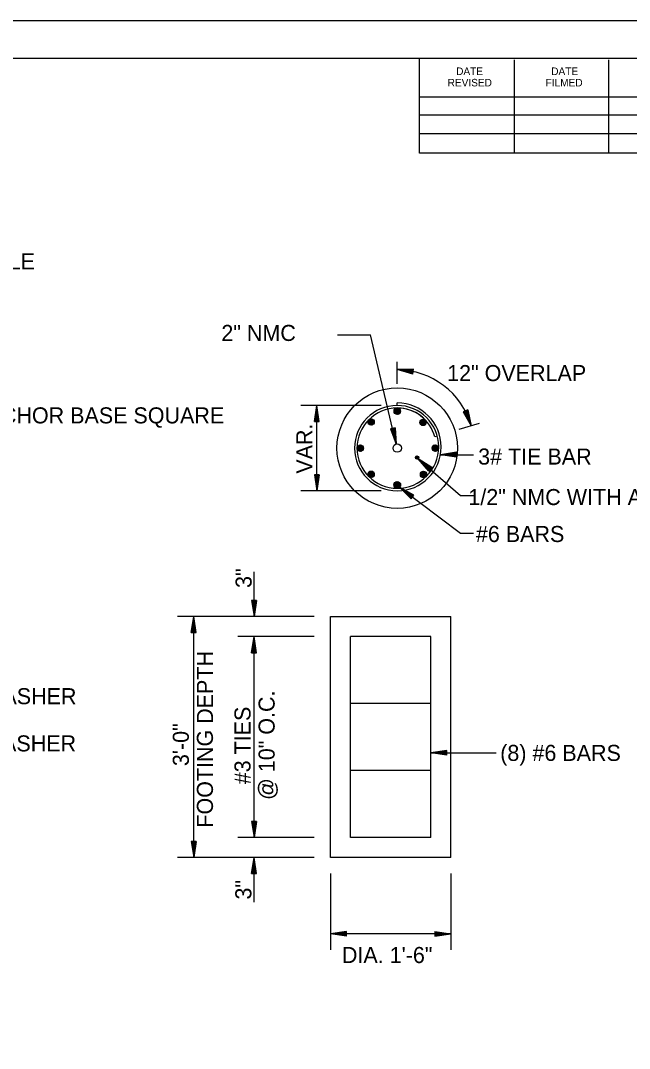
# Model space of a CAD drawing. Extents: x 1370140 to 1371141, y 380020 to 380660.
# Drawn here: x 1370755.4 to 1370944.8, y 380340 to 380660 of the extents above; entities that cross this region are included whole.
import ezdxf

# ---------------------------------------------------------------- set-up
doc = ezdxf.new("R2010")
doc.units = 0
for name, color, linetype in [('R_Border', 7, 'Continuous'), ('R_Draft', 7, 'Continuous'), ('R_No Plot', 7, 'Continuous')]:
    doc.layers.add(name, color=color, linetype=linetype)

msp = doc.modelspace()

# ---------------------------------------------------------------- linework, layer by layer
at = {"layer": 'R_Border'}
for p, q in [((1370177.71, 380648.36), (1371126.25, 380648.36)), ((1370879.47, 380618.72), (1370879.47, 380648.36)), ((1370909.05, 380618.72), (1370909.05, 380647.76)), ((1370938.33, 380618.72), (1370938.33, 380647.76)), ((1370879.47, 380636.3), (1370996.95, 380636.3)), ((1370879.47, 380630.72), (1370996.95, 380630.72)), ((1370879.47, 380618.72), (1370879.47, 380624.9)), ((1370879.47, 380624.9), (1370996.95, 380624.9)), ((1371126.25, 380618.72), (1370879.47, 380618.72))]:
    msp.add_line(p, q, dxfattribs=at)
at = {"layer": 'R_Draft'}
for p, q in [((1370853.99, 380562.21), (1370864.22, 380562.21)), ((1370872.25, 380528.19), (1370864.22, 380562.21)), ((1370872.55, 380546.92), (1370872.55, 380553.77)), ((1370877.61, 380551.48), (1370872.55, 380551.37)), ((1370877.42, 380549.99), (1370872.55, 380551.37)), ((1370877.59, 380551.36), (1370873.38, 380551.27)), ((1370877.43, 380550.12), (1370873.38, 380551.27)), ((1370877.58, 380551.23), (1370874.23, 380551.16)), ((1370877.45, 380550.24), (1370874.23, 380551.16)), ((1370877.56, 380551.11), (1370875.06, 380551.05)), ((1370877.47, 380550.37), (1370875.06, 380551.05)), ((1370877.54, 380550.98), (1370875.9, 380550.94)), ((1370877.48, 380550.5), (1370875.9, 380550.94)), ((1370877.53, 380550.85), (1370876.73, 380550.84)), ((1370877.5, 380550.62), (1370876.73, 380550.84)), ((1370877.42, 380549.99), (1370877.61, 380551.48)), ((1370867.55, 380540.2), (1370842.55, 380540.2)), ((1370846.8, 380535.2), (1370847.55, 380540.2)), ((1370846.92, 380535.2), (1370847.55, 380539.37)), ((1370847.55, 380513.64), (1370847.55, 380540.2)), ((1370848.3, 380535.2), (1370847.55, 380540.2)), ((1370848.17, 380535.2), (1370847.55, 380539.37)), ((1370871.55, 380538.38), (1370872.59, 380539.42)), ((1370871.56, 380538.56), (1370872.41, 380539.41)), ((1370871.57, 380538.22), (1370872.75, 380539.4)), ((1370871.61, 380538.08), (1370872.89, 380539.36)), ((1370871.62, 380538.81), (1370872.16, 380539.34)), ((1370871.66, 380537.96), (1370873.01, 380539.31)), ((1370871.73, 380537.85), (1370873.12, 380539.24)), ((1370871.81, 380537.75), (1370873.22, 380539.16)), ((1370871.89, 380537.66), (1370873.31, 380539.07)), ((1370872, 380537.59), (1370873.38, 380538.97)), ((1370872.11, 380537.52), (1370873.45, 380538.86)), ((1370872.55, 380540.2), (1370872.55, 380540.99)), ((1370847.05, 380535.2), (1370847.55, 380538.51)), ((1370847.17, 380535.2), (1370847.55, 380537.68)), ((1370847.3, 380535.2), (1370847.55, 380536.83)), ((1370847.43, 380535.2), (1370847.55, 380535.99)), ((1370848.04, 380535.2), (1370847.55, 380538.51)), ((1370847.92, 380535.2), (1370847.55, 380537.68)), ((1370847.79, 380535.2), (1370847.55, 380536.83)), ((1370847.66, 380535.2), (1370847.55, 380535.99)), ((1370863.42, 380534.93), (1370864.54, 380536.05)), ((1370863.42, 380535.1), (1370864.37, 380536.05)), ((1370863.45, 380534.78), (1370864.69, 380536.02)), ((1370863.45, 380535.3), (1370864.16, 380536.02)), ((1370863.5, 380534.65), (1370864.82, 380535.97)), ((1370863.56, 380534.53), (1370864.93, 380535.91)), ((1370863.6, 380535.64), (1370863.83, 380535.86)), ((1370863.63, 380534.43), (1370865.04, 380535.84)), ((1370863.72, 380534.34), (1370865.13, 380535.75)), ((1370863.81, 380534.26), (1370865.21, 380535.66)), ((1370872.23, 380537.47), (1370873.5, 380538.73)), ((1370872.38, 380537.44), (1370873.53, 380538.59)), ((1370872.54, 380537.42), (1370873.55, 380538.43)), ((1370872.73, 380537.44), (1370873.53, 380538.24)), ((1370873, 380537.53), (1370873.44, 380537.97)), ((1370879.57, 380534.85), (1370880.66, 380535.94)), ((1370879.57, 380535.03), (1370880.48, 380535.94)), ((1370879.6, 380534.7), (1370880.81, 380535.91)), ((1370879.61, 380535.25), (1370880.26, 380535.89)), ((1370879.64, 380534.56), (1370880.94, 380535.87)), ((1370879.7, 380534.45), (1370881.06, 380535.81)), ((1370879.77, 380534.34), (1370881.17, 380535.74)), ((1370879.85, 380534.24), (1370881.26, 380535.66)), ((1370894.5, 380538.81), (1370893.09, 380538.27)), ((1370893.09, 380538.27), (1370895.58, 380533.87)), ((1370893.21, 380538.32), (1370895.28, 380534.65)), ((1370893.33, 380538.36), (1370894.98, 380535.46)), ((1370893.45, 380538.41), (1370894.68, 380536.23)), ((1370893.57, 380538.45), (1370894.38, 380537.02)), ((1370893.69, 380538.5), (1370894.08, 380537.8)), ((1370893.9, 380538.58), (1370894.08, 380537.8)), ((1370894.02, 380538.63), (1370894.38, 380537.02)), ((1370894.14, 380538.68), (1370894.68, 380536.23)), ((1370894.26, 380538.72), (1370894.98, 380535.46)), ((1370894.38, 380538.77), (1370895.28, 380534.65)), ((1370894.5, 380538.81), (1370895.58, 380533.87)), ((1370846.8, 380535.2), (1370848.3, 380535.2)), ((1370863.92, 380534.19), (1370865.28, 380535.55)), ((1370864.04, 380534.13), (1370865.34, 380535.43)), ((1370864.17, 380534.08), (1370865.38, 380535.3)), ((1370864.32, 380534.06), (1370865.41, 380535.15)), ((1370864.5, 380534.06), (1370865.41, 380534.97)), ((1370864.72, 380534.1), (1370865.37, 380534.75)), ((1370871.86, 380533.23), (1370870.4, 380532.9)), ((1370870.4, 380532.9), (1370872.25, 380528.19)), ((1370870.52, 380532.92), (1370872.06, 380529)), ((1370870.65, 380532.95), (1370871.87, 380529.84)), ((1370870.77, 380532.98), (1370871.68, 380530.65)), ((1370870.89, 380533.01), (1370871.49, 380531.48)), ((1370871.02, 380533.04), (1370871.31, 380532.29)), ((1370871.25, 380533.09), (1370871.31, 380532.29)), ((1370871.37, 380533.12), (1370871.49, 380531.48)), ((1370871.49, 380533.15), (1370871.68, 380530.65)), ((1370871.62, 380533.17), (1370871.87, 380529.84)), ((1370871.74, 380533.2), (1370872.06, 380529)), ((1370871.86, 380533.23), (1370872.25, 380528.19)), ((1370879.94, 380534.16), (1370881.35, 380535.57)), ((1370880.04, 380534.09), (1370881.42, 380535.46)), ((1370880.16, 380534.03), (1370881.48, 380535.35)), ((1370880.29, 380533.98), (1370881.53, 380535.22)), ((1370880.44, 380533.95), (1370881.56, 380535.07)), ((1370880.61, 380533.94), (1370881.56, 380534.9)), ((1370880.81, 380533.97), (1370881.53, 380534.69)), ((1370881.14, 380534.12), (1370881.38, 380534.36)), ((1370897.98, 380534.59), (1370891.69, 380532.7)), ((1370884.99, 380530.68), (1370884.24, 380530.45)), ((1370860.05, 380526.97), (1370861, 380527.92)), ((1370860.05, 380526.8), (1370861.17, 380527.91)), ((1370860.08, 380527.18), (1370860.79, 380527.89)), ((1370860.08, 380526.65), (1370861.32, 380527.88)), ((1370860.13, 380526.52), (1370861.45, 380527.84)), ((1370860.19, 380526.41), (1370861.56, 380527.78)), ((1370860.25, 380527.53), (1370860.44, 380527.72)), ((1370860.26, 380526.3), (1370861.67, 380527.71)), ((1370860.35, 380526.21), (1370861.76, 380527.62)), ((1370860.44, 380526.13), (1370861.84, 380527.53)), ((1370860.55, 380526.06), (1370861.91, 380527.42)), ((1370860.67, 380526), (1370861.97, 380527.3)), ((1370860.8, 380525.95), (1370862.02, 380527.17)), ((1370860.95, 380525.93), (1370862.04, 380527.02)), ((1370861.12, 380525.92), (1370862.04, 380526.85)), ((1370861.34, 380525.97), (1370862, 380526.63)), ((1370883.39, 380526.93), (1370884.38, 380527.92)), ((1370883.4, 380526.77), (1370884.54, 380527.91)), ((1370883.41, 380527.13), (1370884.18, 380527.9)), ((1370883.44, 380526.63), (1370884.69, 380527.88)), ((1370883.48, 380526.5), (1370884.81, 380527.83)), ((1370883.53, 380527.42), (1370883.89, 380527.79)), ((1370883.55, 380526.38), (1370884.93, 380527.76)), ((1370883.62, 380526.28), (1370885.03, 380527.69)), ((1370883.71, 380526.19), (1370885.12, 380527.6)), ((1370883.8, 380526.11), (1370885.2, 380527.51)), ((1370883.91, 380526.04), (1370885.27, 380527.4)), ((1370884.03, 380525.99), (1370885.33, 380527.28)), ((1370884.17, 380525.95), (1370885.37, 380527.14)), ((1370884.32, 380525.92), (1370885.39, 380526.99)), ((1370884.51, 380525.93), (1370885.38, 380526.81)), ((1370884.74, 380525.98), (1370885.33, 380526.57)), ((1370878.19, 380524.01), (1370878.7, 380524.53)), ((1370878.21, 380523.85), (1370878.86, 380524.5)), ((1370878.25, 380524.24), (1370878.47, 380524.47)), ((1370878.26, 380523.73), (1370878.98, 380524.45)), ((1370878.34, 380523.63), (1370879.08, 380524.37)), ((1370878.44, 380523.56), (1370879.16, 380524.27)), ((1370878.57, 380523.5), (1370879.21, 380524.15)), ((1370878.72, 380523.48), (1370879.23, 380523.99)), ((1370878.97, 380523.55), (1370879.16, 380523.74)), ((1370879.08, 380523.63), (1370892.22, 380512.15)), ((1370882.37, 380519.79), (1370879.08, 380523.63)), ((1370883.35, 380520.93), (1370879.08, 380523.63)), ((1370882.45, 380519.89), (1370879.71, 380523.08)), ((1370883.27, 380520.83), (1370879.71, 380523.08)), ((1370891, 380525.62), (1370886, 380524.87)), ((1370886, 380524.87), (1370896.23, 380524.87)), ((1370891, 380524.12), (1370886, 380524.87)), ((1370891, 380525.49), (1370886.84, 380524.87)), ((1370891, 380524.24), (1370886.84, 380524.87)), ((1370891, 380525.36), (1370887.7, 380524.87)), ((1370891, 380524.37), (1370887.7, 380524.87)), ((1370891, 380525.24), (1370888.53, 380524.87)), ((1370891, 380524.49), (1370888.53, 380524.87)), ((1370891, 380525.11), (1370889.38, 380524.87)), ((1370891, 380524.62), (1370889.38, 380524.87)), ((1370891, 380524.98), (1370890.21, 380524.87)), ((1370891, 380524.75), (1370890.21, 380524.87)), ((1370891, 380524.12), (1370891, 380525.62)), ((1370863.42, 380518.7), (1370864.51, 380519.79)), ((1370863.42, 380518.87), (1370864.33, 380519.79)), ((1370863.45, 380518.55), (1370864.66, 380519.76)), ((1370863.46, 380519.09), (1370864.11, 380519.74)), ((1370863.49, 380518.41), (1370864.79, 380519.72)), ((1370863.55, 380518.29), (1370864.91, 380519.66)), ((1370879.73, 380518.79), (1370880.68, 380519.74)), ((1370879.74, 380518.62), (1370880.85, 380519.73)), ((1370879.76, 380519), (1370880.47, 380519.71)), ((1370879.76, 380518.47), (1370881, 380519.7)), ((1370879.81, 380518.34), (1370881.13, 380519.66)), ((1370883.19, 380520.73), (1370880.36, 380522.52)), ((1370882.54, 380519.98), (1370880.36, 380522.52)), ((1370882.62, 380520.08), (1370880.99, 380521.97)), ((1370883.1, 380520.64), (1370880.99, 380521.97)), ((1370883.02, 380520.54), (1370881.63, 380521.42)), ((1370882.7, 380520.17), (1370881.63, 380521.42)), ((1370882.94, 380520.45), (1370882.26, 380520.87)), ((1370882.78, 380520.27), (1370882.26, 380520.87)), ((1370882.37, 380519.79), (1370883.35, 380520.93)), ((1370846.8, 380518.64), (1370847.55, 380513.64)), ((1370848.3, 380518.64), (1370846.8, 380518.64)), ((1370846.92, 380518.64), (1370847.55, 380514.47)), ((1370847.05, 380518.64), (1370847.55, 380515.33)), ((1370847.17, 380518.64), (1370847.55, 380516.17)), ((1370847.3, 380518.64), (1370847.55, 380517.01)), ((1370847.43, 380518.64), (1370847.55, 380517.85)), ((1370848.3, 380518.64), (1370847.55, 380513.64)), ((1370847.79, 380518.64), (1370847.55, 380517.01)), ((1370848.04, 380518.64), (1370847.55, 380515.33)), ((1370848.17, 380518.64), (1370847.55, 380514.47)), ((1370847.92, 380518.64), (1370847.55, 380516.17)), ((1370847.66, 380518.64), (1370847.55, 380517.85)), ((1370863.62, 380518.19), (1370865.02, 380519.59)), ((1370863.7, 380518.09), (1370865.11, 380519.51)), ((1370863.79, 380518.01), (1370865.2, 380519.41)), ((1370863.9, 380517.94), (1370865.27, 380519.31)), ((1370864.01, 380517.87), (1370865.33, 380519.19)), ((1370864.14, 380517.83), (1370865.38, 380519.06)), ((1370864.29, 380517.8), (1370865.41, 380518.92)), ((1370864.46, 380517.79), (1370865.41, 380518.75)), ((1370864.66, 380517.82), (1370865.38, 380518.54)), ((1370865, 380517.98), (1370865.23, 380518.21)), ((1370871.51, 380515.37), (1370872.64, 380516.5)), ((1370871.51, 380515.54), (1370872.47, 380516.5)), ((1370871.53, 380515.22), (1370872.79, 380516.48)), ((1370871.55, 380515.76), (1370872.25, 380516.46)), ((1370871.58, 380515.08), (1370872.93, 380516.43)), ((1370879.87, 380518.22), (1370881.24, 380519.6)), ((1370879.93, 380519.34), (1370880.13, 380519.54)), ((1370879.94, 380518.12), (1370881.35, 380519.52)), ((1370880.03, 380518.03), (1370881.44, 380519.44)), ((1370880.12, 380517.94), (1370881.52, 380519.35)), ((1370880.23, 380517.87), (1370881.59, 380519.24)), ((1370880.35, 380517.82), (1370881.65, 380519.12)), ((1370880.48, 380517.77), (1370881.7, 380518.99)), ((1370880.63, 380517.75), (1370881.72, 380518.84)), ((1370880.81, 380517.74), (1370881.72, 380518.66)), ((1370881.02, 380517.79), (1370881.68, 380518.44)), ((1370867.55, 380513.64), (1370842.55, 380513.64)), ((1370871.63, 380514.96), (1370873.05, 380516.38)), ((1370871.7, 380514.85), (1370873.16, 380516.31)), ((1370871.78, 380514.76), (1370873.25, 380516.23)), ((1370871.78, 380516.17), (1370871.84, 380516.23)), ((1370871.87, 380514.67), (1370873.34, 380516.14)), ((1370871.97, 380514.59), (1370873.42, 380516.04)), ((1370872.09, 380514.53), (1370873.48, 380515.92)), ((1370872.21, 380514.48), (1370873.53, 380515.8)), ((1370872.35, 380514.44), (1370873.57, 380515.66)), ((1370872.51, 380514.42), (1370873.59, 380515.5)), ((1370872.7, 380514.43), (1370873.58, 380515.31)), ((1370872.94, 380514.5), (1370873.51, 380515.07)), ((1370873.29, 380514.73), (1370892.22, 380500.42)), ((1370876.84, 380511.13), (1370873.29, 380514.73)), ((1370877.74, 380512.32), (1370873.29, 380514.73)), ((1370876.91, 380511.23), (1370873.96, 380514.23)), ((1370877.66, 380512.23), (1370873.96, 380514.23)), ((1370877.59, 380512.12), (1370874.65, 380513.71)), ((1370876.99, 380511.33), (1370874.65, 380513.71)), ((1370877.06, 380511.43), (1370875.31, 380513.21)), ((1370877.51, 380512.02), (1370875.31, 380513.21)), ((1370877.44, 380511.92), (1370875.99, 380512.7)), ((1370877.14, 380511.53), (1370875.99, 380512.7)), ((1370877.36, 380511.82), (1370876.66, 380512.2)), ((1370877.22, 380511.63), (1370876.66, 380512.2)), ((1370876.84, 380511.13), (1370877.74, 380512.32)), ((1370892.22, 380512.15), (1370896.23, 380512.15)), ((1370892.22, 380500.42), (1370896.23, 380500.42)), ((1370827.99, 380474.48), (1370827.99, 380488.37)), ((1370827.24, 380479.48), (1370827.99, 380474.48)), ((1370828.74, 380479.48), (1370827.24, 380479.48)), ((1370827.36, 380479.48), (1370827.99, 380475.31)), ((1370827.49, 380479.48), (1370827.99, 380476.17)), ((1370827.62, 380479.48), (1370827.99, 380477)), ((1370827.74, 380479.48), (1370827.99, 380477.85)), ((1370827.87, 380479.48), (1370827.99, 380478.69)), ((1370828.74, 380479.48), (1370827.99, 380474.48)), ((1370828.23, 380479.48), (1370827.99, 380477.85)), ((1370828.49, 380479.48), (1370827.99, 380476.17)), ((1370828.61, 380479.48), (1370827.99, 380475.31)), ((1370828.36, 380479.48), (1370827.99, 380477)), ((1370828.11, 380479.48), (1370827.99, 380478.69)), ((1370846.74, 380474.48), (1370804.24, 380474.48)), ((1370808.49, 380469.48), (1370809.24, 380474.48)), ((1370808.61, 380469.48), (1370809.24, 380473.64)), ((1370808.74, 380469.48), (1370809.24, 380472.78)), ((1370808.87, 380469.48), (1370809.24, 380471.95)), ((1370809.24, 380399.48), (1370809.24, 380474.48)), ((1370809.99, 380469.48), (1370809.24, 380474.48)), ((1370809.86, 380469.48), (1370809.24, 380473.64)), ((1370809.74, 380469.48), (1370809.24, 380472.78)), ((1370809.61, 380469.48), (1370809.24, 380471.95)), ((1370851.74, 380399.48), (1370851.74, 380474.48)), ((1370851.74, 380474.48), (1370889.24, 380474.48)), ((1370889.24, 380399.48), (1370889.24, 380474.48)), ((1370808.49, 380469.48), (1370809.99, 380469.48)), ((1370809, 380469.48), (1370809.24, 380471.1)), ((1370809.12, 380469.48), (1370809.24, 380470.27)), ((1370809.48, 380469.48), (1370809.24, 380471.1)), ((1370809.36, 380469.48), (1370809.24, 380470.27)), ((1370846.74, 380468.23), (1370822.99, 380468.23)), ((1370827.24, 380463.23), (1370827.99, 380468.23)), ((1370827.36, 380463.23), (1370827.99, 380467.39)), ((1370827.49, 380463.23), (1370827.99, 380466.53)), ((1370827.62, 380463.23), (1370827.99, 380465.7)), ((1370827.99, 380405.73), (1370827.99, 380468.23)), ((1370828.74, 380463.23), (1370827.99, 380468.23)), ((1370828.61, 380463.23), (1370827.99, 380467.39)), ((1370828.49, 380463.23), (1370827.99, 380466.53)), ((1370828.36, 380463.23), (1370827.99, 380465.7)), ((1370882.99, 380468.23), (1370857.99, 380468.23)), ((1370857.99, 380405.73), (1370857.99, 380468.23)), ((1370882.99, 380405.73), (1370882.99, 380468.23)), ((1370827.24, 380463.23), (1370828.74, 380463.23)), ((1370827.75, 380463.23), (1370827.99, 380464.85)), ((1370827.87, 380463.23), (1370827.99, 380464.02)), ((1370828.23, 380463.23), (1370827.99, 380464.85)), ((1370828.11, 380463.23), (1370827.99, 380464.02)), ((1370882.99, 380447.39), (1370857.99, 380447.39)), ((1370888, 380432.79), (1370883, 380432.04)), ((1370888, 380431.29), (1370883, 380432.04)), ((1370883, 380432.04), (1370903.36, 380432.04)), ((1370888, 380432.67), (1370883.84, 380432.04)), ((1370888, 380431.42), (1370883.84, 380432.04)), ((1370888, 380432.54), (1370884.7, 380432.04)), ((1370888, 380431.54), (1370884.7, 380432.04)), ((1370888, 380432.41), (1370885.53, 380432.04)), ((1370888, 380431.67), (1370885.53, 380432.04)), ((1370888, 380432.29), (1370886.38, 380432.04)), ((1370888, 380431.8), (1370886.38, 380432.04)), ((1370888, 380432.16), (1370887.21, 380432.04)), ((1370888, 380431.92), (1370887.21, 380432.04)), ((1370888, 380431.29), (1370888, 380432.79)), ((1370882.99, 380426.56), (1370857.99, 380426.56)), ((1370827.24, 380410.73), (1370827.99, 380405.73)), ((1370828.74, 380410.73), (1370827.24, 380410.73)), ((1370827.36, 380410.73), (1370827.99, 380406.56)), ((1370827.49, 380410.73), (1370827.99, 380407.42)), ((1370827.62, 380410.73), (1370827.99, 380408.25)), ((1370827.74, 380410.73), (1370827.99, 380409.1)), ((1370827.87, 380410.73), (1370827.99, 380409.94)), ((1370828.74, 380410.73), (1370827.99, 380405.73)), ((1370828.23, 380410.73), (1370827.99, 380409.1)), ((1370828.49, 380410.73), (1370827.99, 380407.42)), ((1370828.61, 380410.73), (1370827.99, 380406.56)), ((1370828.36, 380410.73), (1370827.99, 380408.25)), ((1370828.11, 380410.73), (1370827.99, 380409.94)), ((1370808.49, 380404.48), (1370809.24, 380399.48)), ((1370809.99, 380404.48), (1370808.49, 380404.48)), ((1370808.61, 380404.48), (1370809.24, 380400.31)), ((1370808.74, 380404.48), (1370809.24, 380401.17)), ((1370808.87, 380404.48), (1370809.24, 380402)), ((1370808.99, 380404.48), (1370809.24, 380402.85)), ((1370809.12, 380404.48), (1370809.24, 380403.69)), ((1370809.99, 380404.48), (1370809.24, 380399.48)), ((1370809.48, 380404.48), (1370809.24, 380402.85)), ((1370809.74, 380404.48), (1370809.24, 380401.17)), ((1370809.86, 380404.48), (1370809.24, 380400.31)), ((1370809.61, 380404.48), (1370809.24, 380402)), ((1370809.36, 380404.48), (1370809.24, 380403.69)), ((1370846.74, 380405.73), (1370822.99, 380405.73)), ((1370882.99, 380405.73), (1370857.99, 380405.73)), ((1370846.74, 380399.48), (1370804.24, 380399.48)), ((1370827.24, 380394.48), (1370827.99, 380399.48)), ((1370827.36, 380394.48), (1370827.99, 380398.64)), ((1370827.99, 380385.58), (1370827.99, 380399.48)), ((1370828.74, 380394.48), (1370827.99, 380399.48)), ((1370828.61, 380394.48), (1370827.99, 380398.64)), ((1370889.24, 380399.48), (1370851.74, 380399.48)), ((1370827.49, 380394.48), (1370827.99, 380397.78)), ((1370827.62, 380394.48), (1370827.99, 380396.95)), ((1370827.75, 380394.48), (1370827.99, 380396.1)), ((1370827.87, 380394.48), (1370827.99, 380395.27)), ((1370828.49, 380394.48), (1370827.99, 380397.78)), ((1370828.36, 380394.48), (1370827.99, 380396.95)), ((1370828.23, 380394.48), (1370827.99, 380396.1)), ((1370828.11, 380394.48), (1370827.99, 380395.27)), ((1370827.24, 380394.48), (1370828.74, 380394.48)), ((1370851.74, 380394.48), (1370851.74, 380370.73)), ((1370889.24, 380394.48), (1370889.24, 380370.73)), ((1370856.74, 380376.48), (1370851.74, 380375.73)), ((1370889.24, 380375.73), (1370851.74, 380375.73)), ((1370856.74, 380374.98), (1370851.74, 380375.73)), ((1370856.74, 380376.35), (1370852.57, 380375.73)), ((1370856.74, 380375.1), (1370852.57, 380375.73)), ((1370856.74, 380376.22), (1370853.43, 380375.73)), ((1370856.74, 380375.23), (1370853.43, 380375.73)), ((1370856.74, 380376.1), (1370854.27, 380375.73)), ((1370856.74, 380375.35), (1370854.27, 380375.73)), ((1370856.74, 380375.97), (1370855.11, 380375.73)), ((1370856.74, 380375.48), (1370855.11, 380375.73)), ((1370856.74, 380375.84), (1370855.95, 380375.73)), ((1370856.74, 380375.61), (1370855.95, 380375.73)), ((1370856.74, 380374.98), (1370856.74, 380376.48)), ((1370884.24, 380376.48), (1370889.24, 380375.73)), ((1370884.24, 380376.48), (1370884.24, 380374.98)), ((1370884.24, 380376.35), (1370888.4, 380375.73)), ((1370884.24, 380376.22), (1370887.54, 380375.73)), ((1370884.24, 380376.1), (1370886.71, 380375.73)), ((1370884.24, 380375.97), (1370885.86, 380375.73)), ((1370884.24, 380375.84), (1370885.03, 380375.73)), ((1370884.24, 380374.98), (1370889.24, 380375.73)), ((1370884.24, 380375.48), (1370885.86, 380375.73)), ((1370884.24, 380375.23), (1370887.54, 380375.73)), ((1370884.24, 380375.1), (1370888.4, 380375.73)), ((1370884.24, 380375.35), (1370886.71, 380375.73)), ((1370884.24, 380375.61), (1370885.03, 380375.73))]:
    msp.add_line(p, q, dxfattribs=at)
for centre, radius in [((1370872.55, 380526.92), 18.75), ((1370872.55, 380538.42), 1), ((1370864.41, 380535.05), 1), ((1370880.57, 380534.94), 1), ((1370861.05, 380526.92), 1), ((1370872.55, 380526.92), 1.3), ((1370884.39, 380526.92), 1), ((1370878.71, 380524), 0.521), ((1370864.41, 380518.79), 1), ((1370880.73, 380518.74), 1), ((1370872.55, 380515.46), 1.04)]:
    msp.add_circle(centre, radius, dxfattribs=at)
for centre, radius, start, end in [((1370872.55, 380527.31), 23.95, 15.8939, 90), ((1370872.55, 380526.92), 13.28, 90, 270), ((1370872.55, 380526.92), 12.5, 90, 270), ((1370872.55, 380527.31), 13.67, 270, 90), ((1370872.55, 380527.31), 12.89, 270, 90), ((1370872.55, 380527.31), 12.11, 43.6894, 90), ((1370872.55, 380527.31), 12.11, 15.0162, 90)]:
    msp.add_arc(centre, radius, start, end, dxfattribs=at)
at = {"layer": 'R_No Plot'}
msp.add_line((1370140.51, 380660.04), (1371140.51, 380660.04), dxfattribs=at)
msp.add_lwpolyline([(1370140.49, 380660.04), (1371140.51, 380660.04), (1371140.51, 380020.03), (1370140.49, 380020.03)], close=True, dxfattribs=at)

# ---------------------------------------------------------------- texts
at = {"layer": 'R_Border'}
for s, p in [('DATE', (1370890.87, 380643.08)), ('DATE', (1370920.45, 380643.08)), ('REVISED', (1370888.23, 380639.54)), ('FILMED', (1370918.71, 380639.54))]:
    msp.add_text(s, height=2.346, dxfattribs=at).set_placement(p)
at = {"layer": 'R_Draft'}
for s, p in [('BOLT CIRCLE', (1370716, 380582.56)), ('2" NMC', (1370817.83, 380560.29)), ('12" OVERLAP', (1370888.07, 380547.79)), ('ANCHOR BASE SQUARE', (1370739.96, 380534.62)), ('3# TIE BAR', (1370897.72, 380521.81)), (' 1/2" NMC WITH A SOLID 1C/#8 A.W.G., E.G.C.', (1370892.81, 380509.19)), ('#6 BARS', (1370897.02, 380497.69)), ('FLAT WASHER', (1370725.21, 380447.2)), ('FLAT WASHER', (1370725.1, 380432.5)), ('(8) #6 BARS', (1370904.58, 380429.54)), ('DIA. 1\'-6"', (1370855.33, 380366.62))]:
    msp.add_text(s, height=5, dxfattribs=at).set_placement(p)
for s, p in [('VAR.', (1370846.13, 380518.97)), ('3"', (1370827.25, 380483.4)), ('FOOTING DEPTH', (1370815.22, 380408.78)), ('@ 10" O.C.', (1370834.41, 380417.4)), ('#3 TIES', (1370826.91, 380422.28)), ('3\'-0"', (1370807.72, 380427.94)), ('3"', (1370827.17, 380386.38))]:
    msp.add_text(s, height=5, rotation=90, dxfattribs=at).set_placement(p)

doc.saveas('drawing.dxf')
